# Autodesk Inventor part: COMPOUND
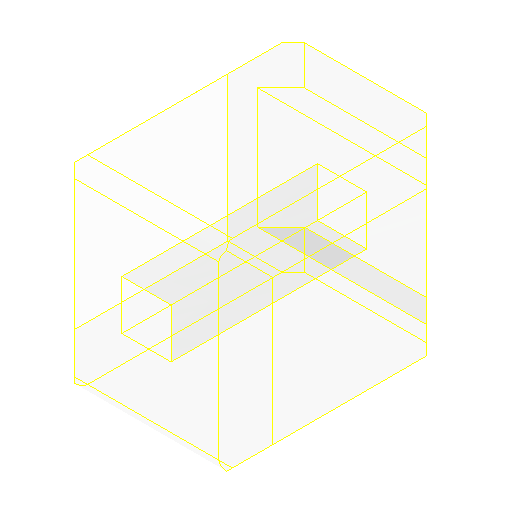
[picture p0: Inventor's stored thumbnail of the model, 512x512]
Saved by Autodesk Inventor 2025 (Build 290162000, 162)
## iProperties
Created: 2025-05
Part Number: COMPOUND
Material: Generico
Document SubType Name: Modeling
Designer: R5800u
Density: 1 g/cm^3
Appearance: Default
Author: R5800u
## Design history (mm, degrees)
feature "Composto1"
node "Superf1"
